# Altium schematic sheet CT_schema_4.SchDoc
size 300 x 247 mm
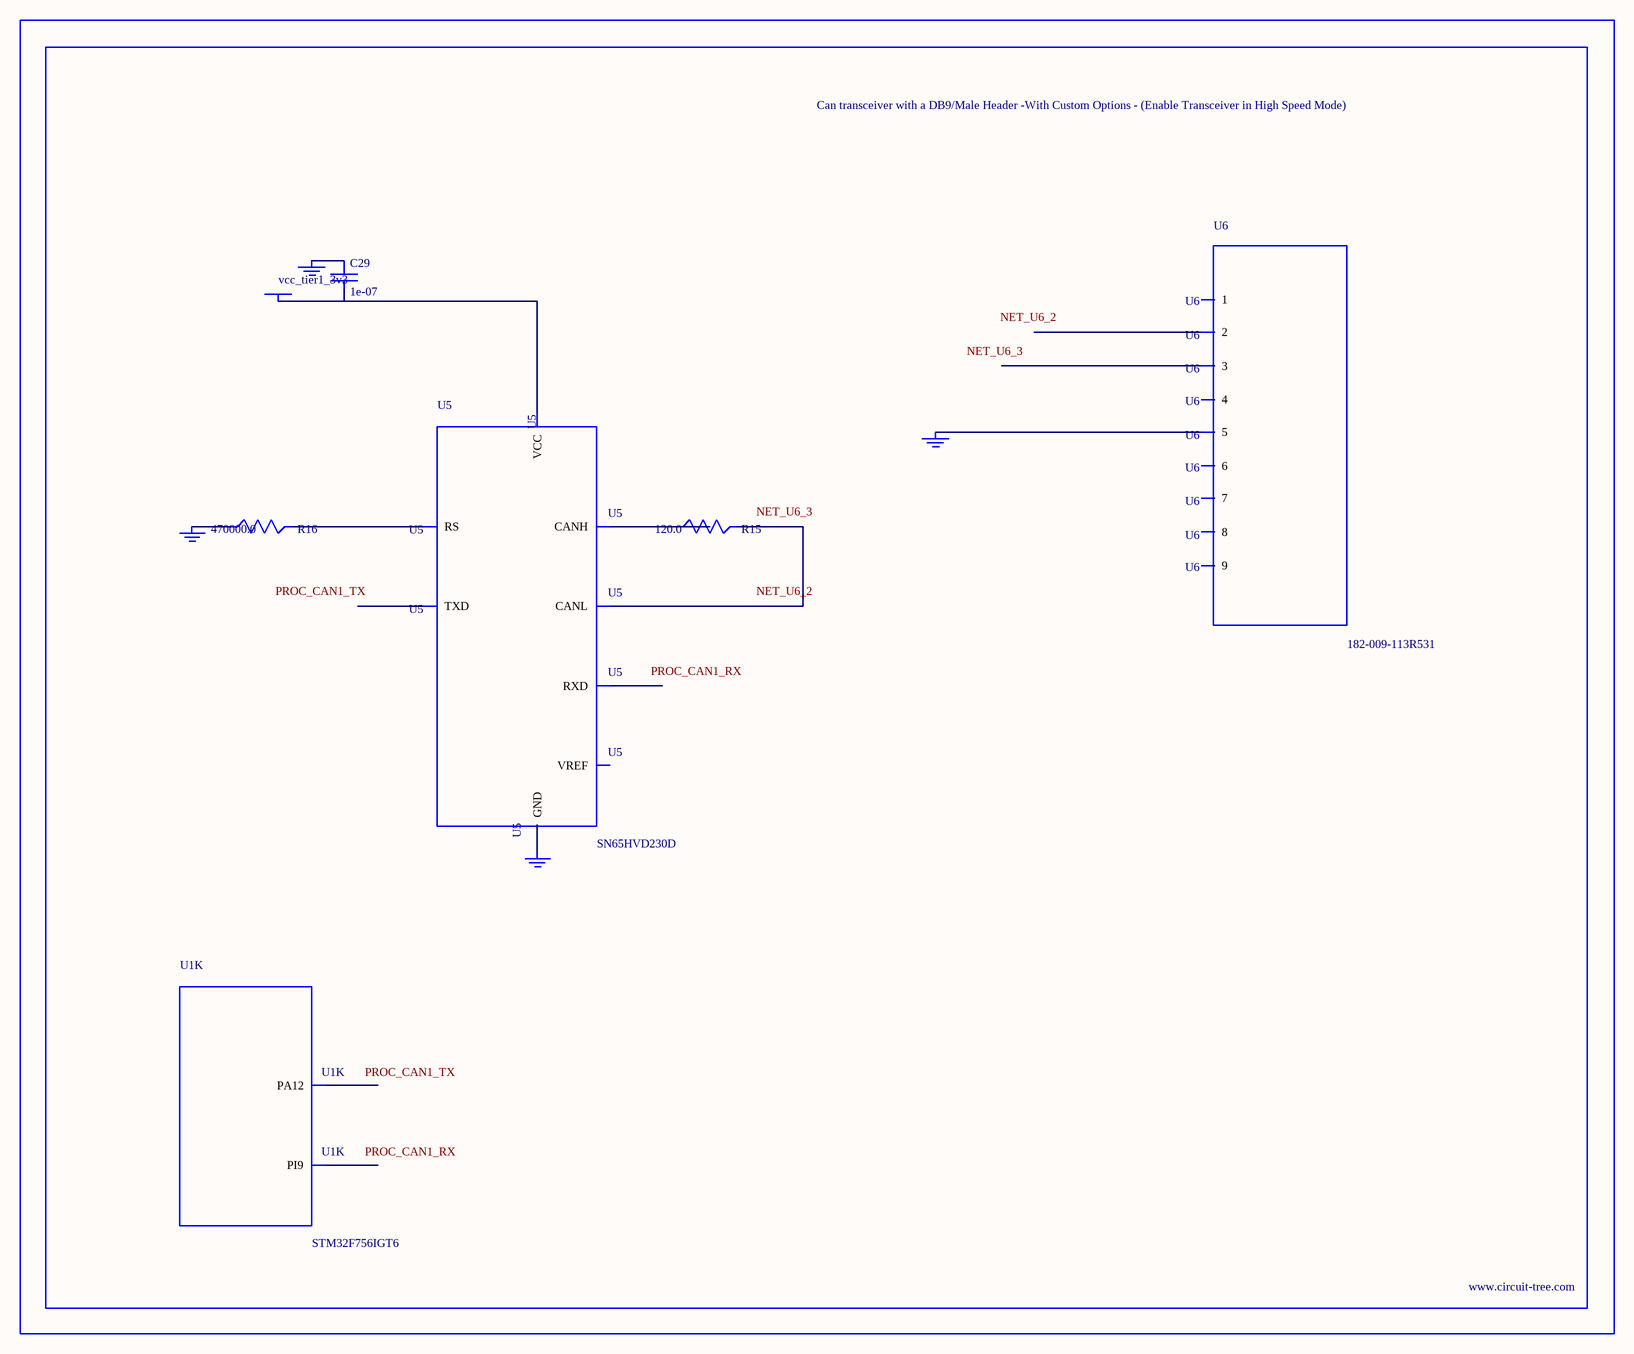
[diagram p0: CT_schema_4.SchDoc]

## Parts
BORDER3  (no value)
C29  1e-07  [C0402]
GND_INSTANCE_3_0  (no value)
GND_INSTANCE_3_1  (no value)
GND_INSTANCE_3_2  (no value)
GND_INSTANCE_3_3  (no value)
POWER_INSTANCE_3_0  vcc_tier1_3v3
R15  120.0  [R0603]
R16  470000.0  [R0603]
U1  STM32F756IGT6  [LQFP176]  (part K of 14)
U5  SN65HVD230D  [SOIC-8]
U6  182-009-113R531  [182-009-MALE]

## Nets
NetC29_1: C29.1 GND_INSTANCE_3_0.0(GND)
NetC29_2: C29.2 POWER_INSTANCE_3_0.0(PWR) U5.3(VCC)
NetGND_INSTANCE_3_1_0: GND_INSTANCE_3_1.0(GND) R16.1
NetGND_INSTANCE_3_2_0: GND_INSTANCE_3_2.0(GND) U5.2(GND)
NetGND_INSTANCE_3_3_0: GND_INSTANCE_3_3.0(GND) U6.5
NetR15_1: R15.1 U5.7(CANH)
NetR15_2: R15.2 U5.6(CANL)
NetR16_2: R16.2 U5.8(RS)

Not connected (* = marked no-connect by the designer): U1 11(PI9) 123(PA12); U5 1(TXD) 4(RXD) 5(VREF); U6 1 2 3 4 6 7 8 9

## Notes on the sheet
- Labels drawn without touching a wire or pin: NET_U6_2, NET_U6_3, PROC_CAN1_RX, PROC_CAN1_TX

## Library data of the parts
BORDER3 = BORDER_PAGE3
C29 = C0402C104K3RACTU
GND_INSTANCE_3_0-GND_INSTANCE_3_3 = GND
POWER_INSTANCE_3_0 = PWR
R15 = RC0603JR-07120RL
R16 = RC0603JR-07470KL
